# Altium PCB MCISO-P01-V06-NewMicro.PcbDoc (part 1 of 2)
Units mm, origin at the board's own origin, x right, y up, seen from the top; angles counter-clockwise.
Board outline 60 x 112.78 mm, 2 copper layers (Top Layer, Bottom Layer), stack 1.57 mm thick; 124 components, 85 nets, 520 pads, 108 vias.
Unrouted connection lines stored in the file: 6.
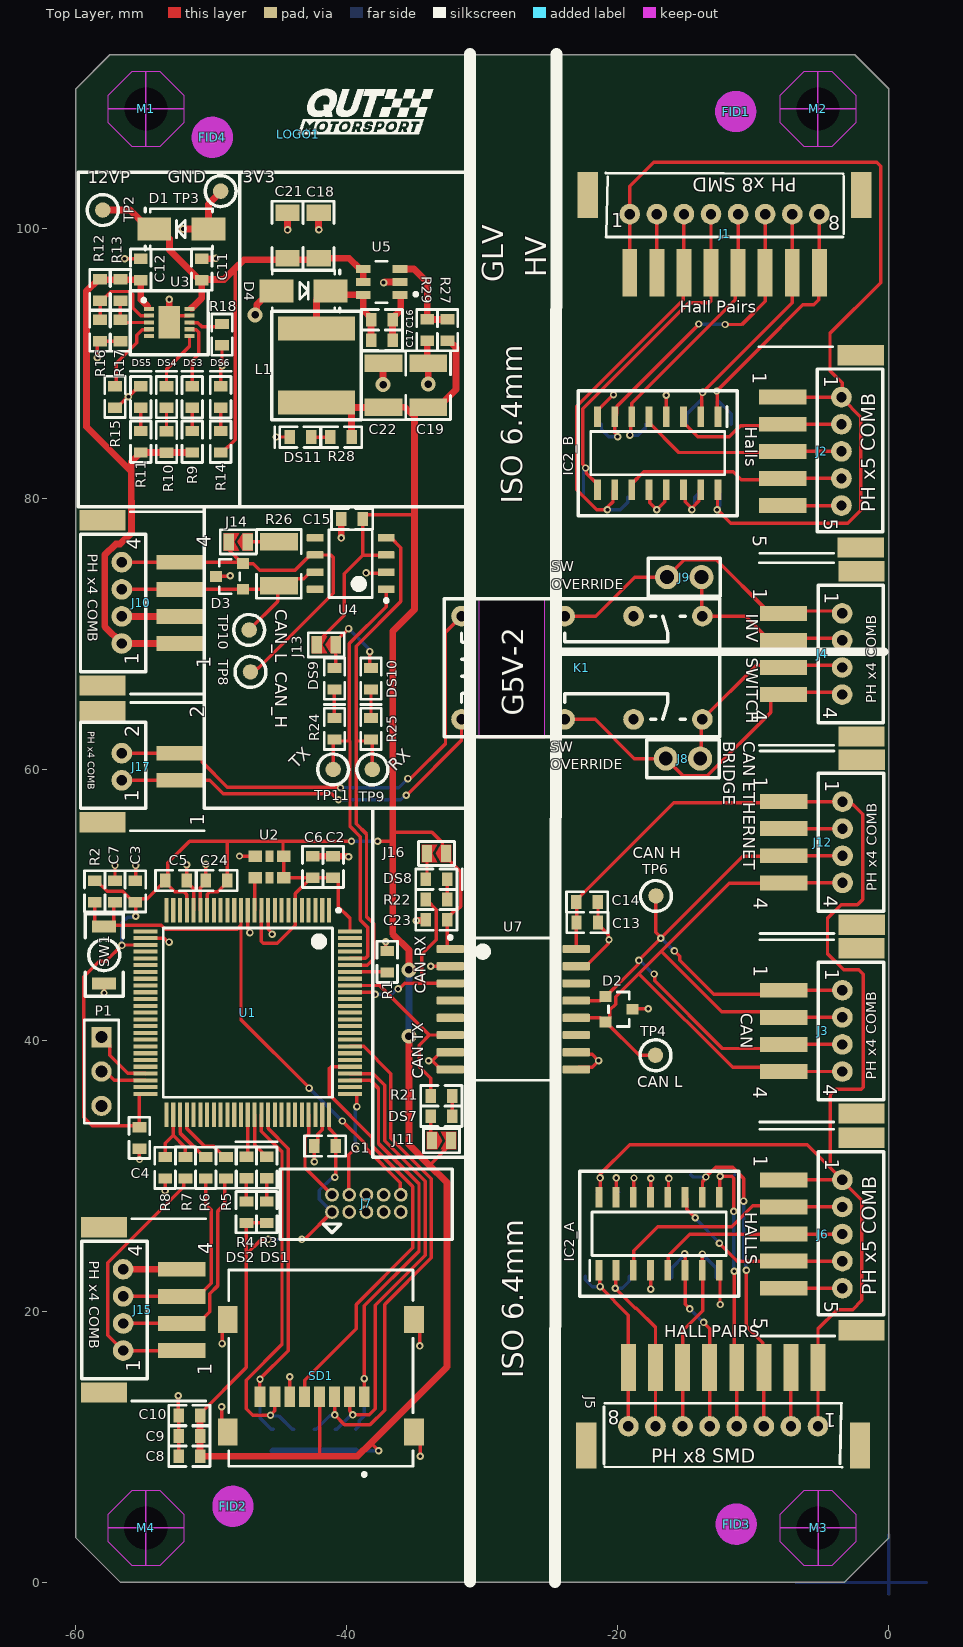
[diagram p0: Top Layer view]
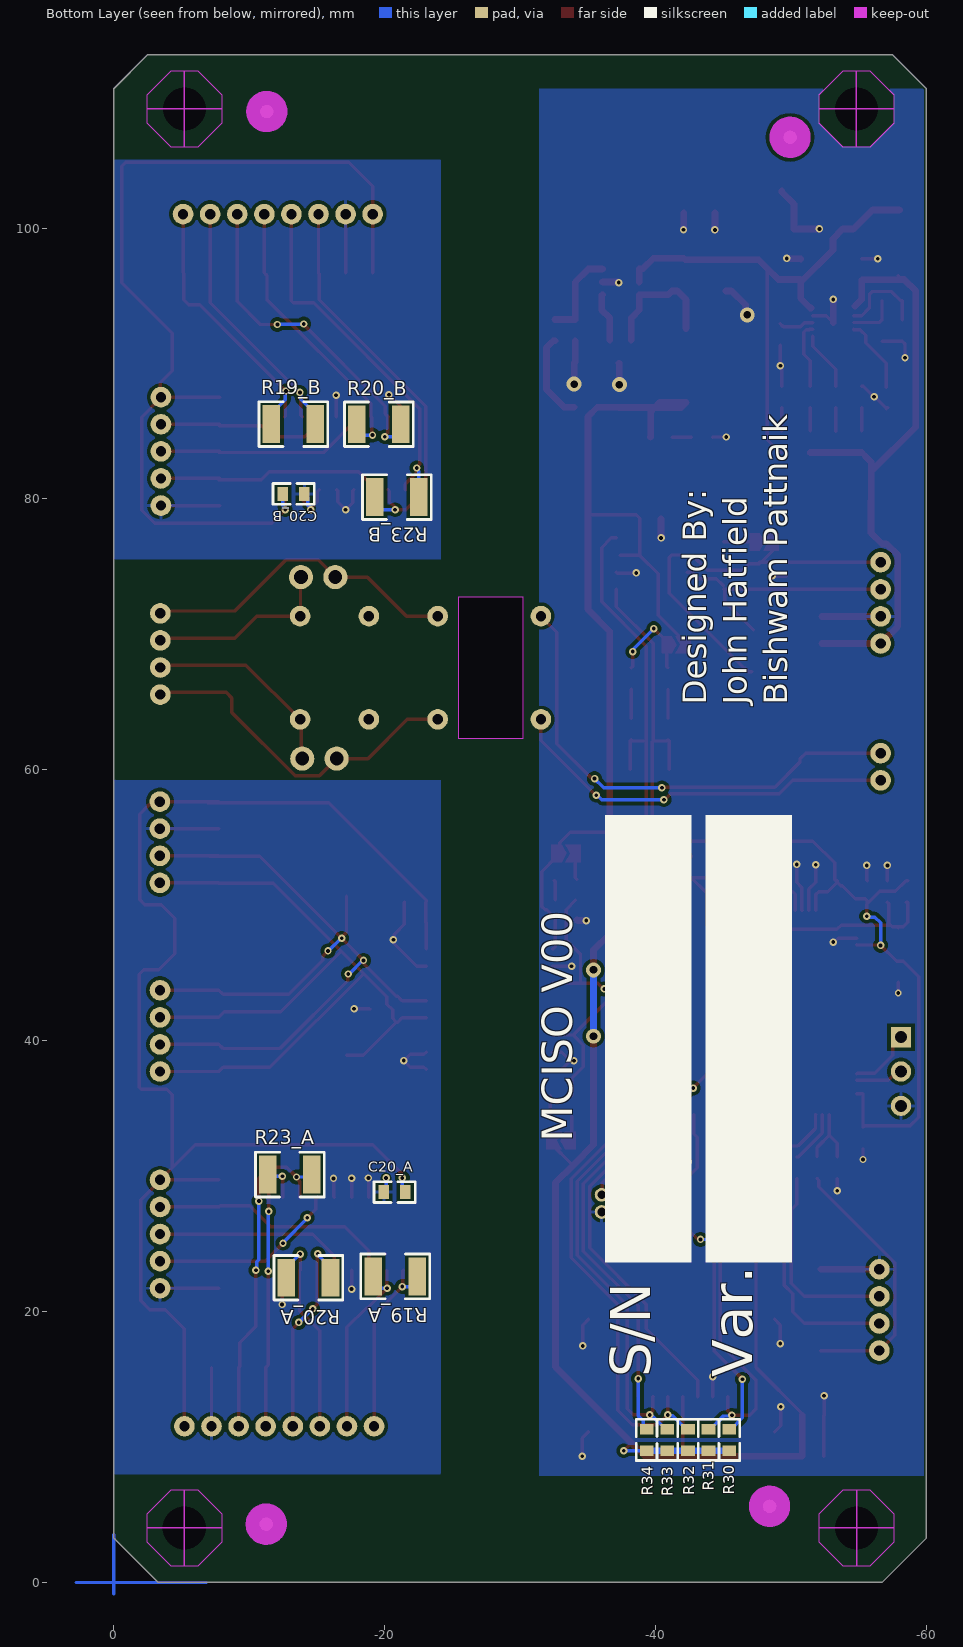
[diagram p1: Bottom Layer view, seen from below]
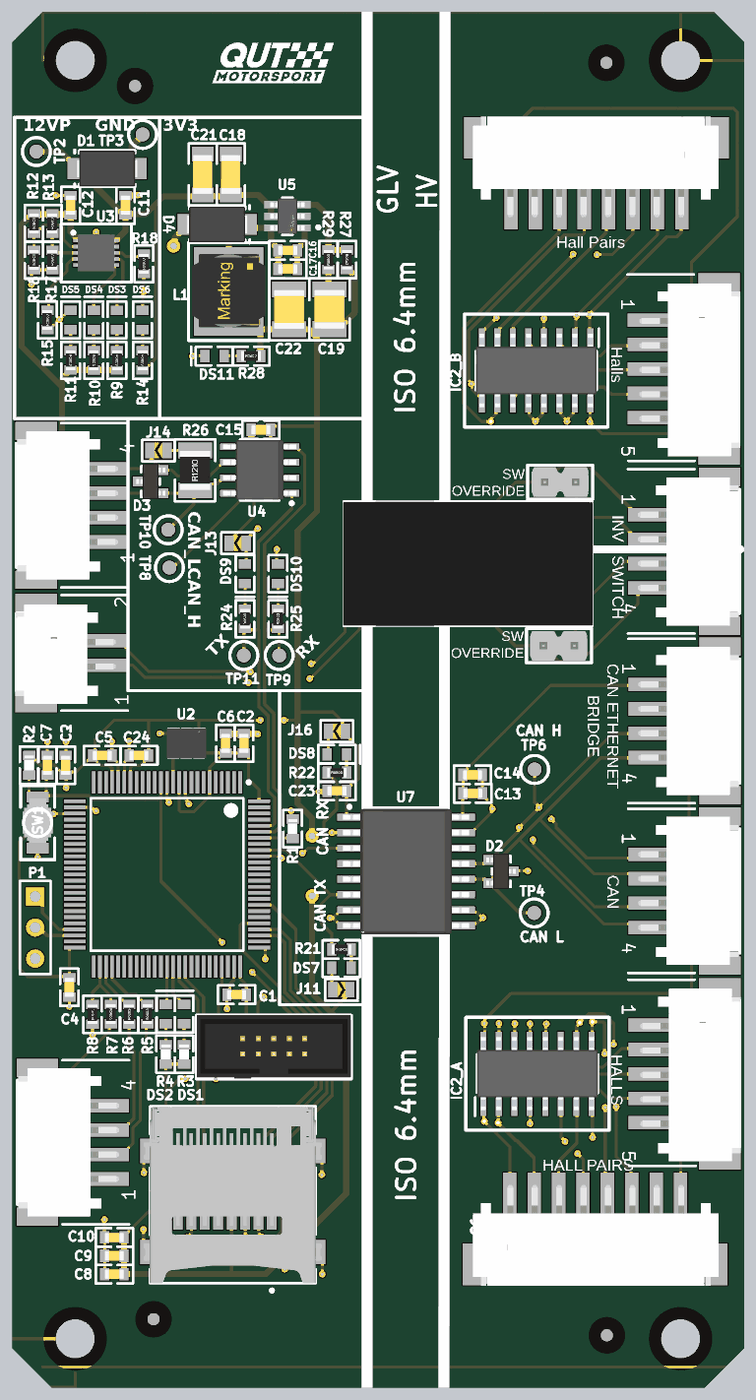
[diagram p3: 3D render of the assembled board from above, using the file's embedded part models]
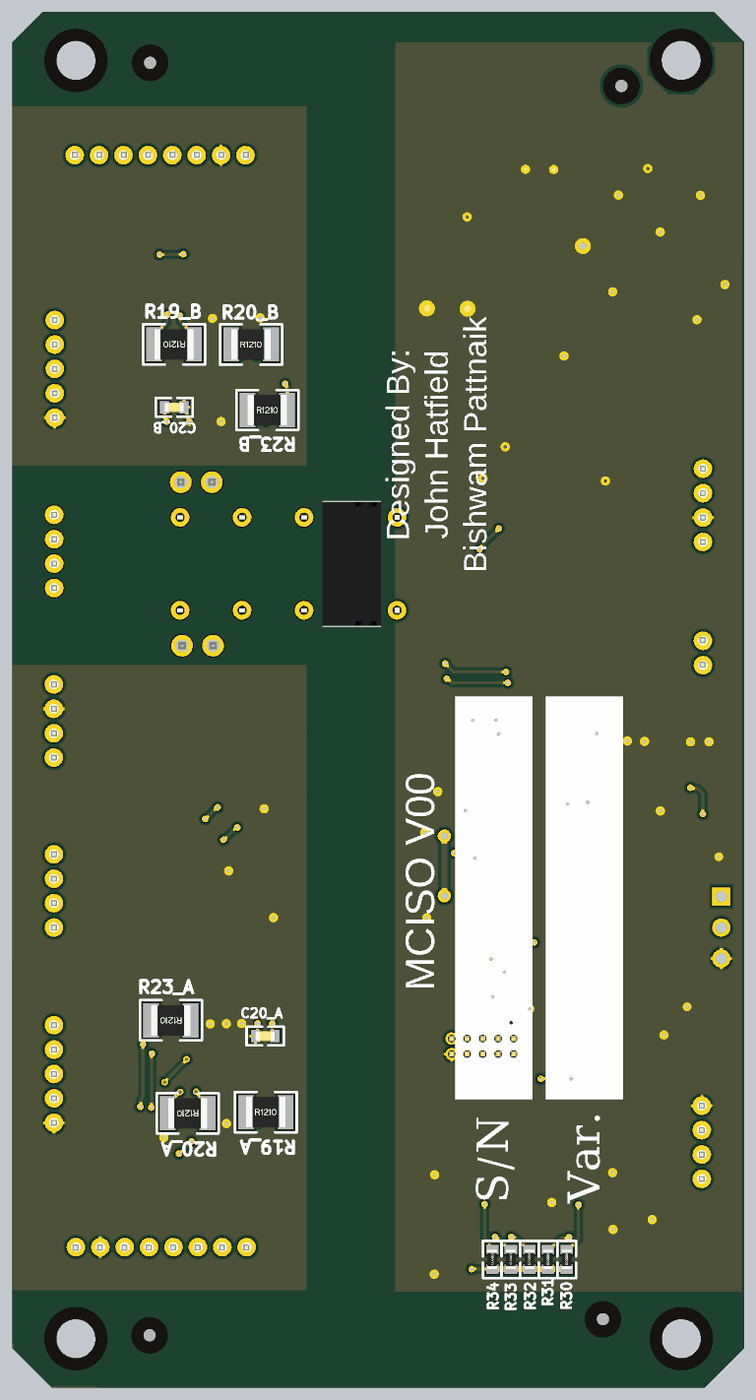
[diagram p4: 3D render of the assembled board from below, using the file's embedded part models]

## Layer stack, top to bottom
Top Solder: solder mask 0.0102, Solder Resist, Dk 3.5
Top Layer: signal copper 0.0356
Dielectric 1: core 1.4986, Core-043, Dk 4.3
Bottom Layer: signal copper 0.0356
Bottom Solder: solder mask 0.0102, Solder Resist, Dk 3.5

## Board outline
-59.993,3.287 -59.993,110.287 -57.493,112.787 -2.493,112.787 0.007,110.287 0.007,3.287 -3.276,0.004 -56.71,0.004
cut-out: -30.211,72.726 -25.411,72.726 -25.411,62.326 -30.211,62.326

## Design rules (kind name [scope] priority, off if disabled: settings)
Clearance [All] p1: gap=0.254 ignorepadtopadclearanceinfootprint=TRUE except(0: Arc-Hole Track-Hole SMDPad-Hole THPad-Hole Via-Hole Fill-Hole Poly-Hole Region-Hole Text-Hole; 0.152: SMDPad-SMDPad; 0.178: Arc-SMDPad Track-SMDPad; 0.2: Arc-Arc Arc-Track Track-Track)
MinimumSolderMaskSliver [All] p1: minsoldermaskwidth=0.1
PolygonConnect PolygonConnect_1 [All] p1: thpad.connectstyle=Relief thpad.reliefconductorwidth=0.254 thpad.reliefentries=4 thpad.polygonreliefangle="90 Angle" thpad.airgapwidth=0.254 smdpad.connectstyle=Relief smdpad.reliefconductorwidth=0.254 smdpad.reliefentries=4 smdpad.polygonreliefangle="90 Angle" smdpad.airgapwidth=0.254 via.connectstyle=Direct via.reliefconductorwidth=0.254 via.reliefentries=4 via.polygonreliefangle="90 Angle" via.airgapwidth=0.254
RoomDefinition Designator [InComponentClass('Designator')] p1 off: confinementstyle=ConfineIn formatcopy=TRUE lockcomponents=FALSE outline -43.811,-14.874 -33.411,-14.874 -33.411,-7.074 -43.811,-7.074
RoomDefinition U_MCISO-S07-V00-Master-PSU3V3-300mA [InComponentClass('U_MCISO-S07-V00-Master-PSU3V3-300mA')] p2 off: confinementstyle=ConfineIn formatcopy=TRUE lockcomponents=FALSE outline -101.811,-42.574 -51.011,-42.574 -51.011,-17.174 -101.811,-17.174
RoomDefinition U_MCISO-S05-V00-CANIsolation [InComponentClass('U_MCISO-S05-V00-CANIsolation')] p3 off: confinementstyle=ConfineIn formatcopy=TRUE lockcomponents=FALSE outline -94.011,15.426 -83.411,15.426 -83.411,22.026 -94.011,22.026
RoomDefinition U_MCISO-S04-V00-Microcontroller [InComponentClass('U_MCISO-S04-V00-Microcontroller')] p4 off: confinementstyle=ConfineIn formatcopy=TRUE lockcomponents=FALSE outline -90.611,-12.974 -82.011,-12.974 -82.011,-7.674 -90.611,-7.674
RoomDefinition U_MCISO-S03-V00-CAN_MAIN [InComponentClass('U_MCISO-S03-V00-CAN_MAIN')] p5 off: confinementstyle=ConfineIn formatcopy=TRUE lockcomponents=FALSE outline -101.311,-13.874 -91.711,-13.874 -91.711,-8.074 -101.311,-8.074
RoomDefinition U_MCISO-S02-V00-12VProtection [InComponentClass('U_MCISO-S02-V00-12VProtection')] p6 off: confinementstyle=ConfineIn formatcopy=TRUE lockcomponents=FALSE outline -51.111,-34.574 -40.811,-34.574 -40.811,-18.274 -51.111,-18.274
RoomDefinition MCISO-S01-V00-Master [InComponentClass('MCISO-S01-V00-Master')] p7 off: confinementstyle=ConfineIn formatcopy=TRUE lockcomponents=FALSE outline -76.211,-4.974 -65.611,-4.974 -65.611,-0.374 -76.211,-0.374
RoomDefinition B [InComponentClass('B')] p8 off: confinementstyle=ConfineIn formatcopy=TRUE lockcomponents=FALSE outline -89.811,-6.074 -82.111,-6.074 -82.111,-0.274 -89.811,-0.274
RoomDefinition A [InComponentClass('A')] p9 off: confinementstyle=ConfineIn formatcopy=TRUE lockcomponents=FALSE outline -101.811,-6.074 -91.511,-6.074 -91.511,0.026 -101.811,0.026
RoutingVias [All] p1: holewidth=0.35 width=0.6 viastyle="Through Hole" minholewidth=0.35 minwidth=0.6 maxholewidth=0.35 maxwidth=0.6
SilkToSilkClearance [All] p1: silktosilkclearance=0
SilkToSolderMaskClearance [IsPad] p1: minsilkscreentomaskgap=0 clearancetoexposedcopper=TRUE
SolderMaskExpansion [All] p1: expansion=0.102 istentingtop=FALSE
Width [All] p1: maxlimit=0.5 minlimit=0.254 preferedwidth=0.254
27 further rules are at their usual default settings.

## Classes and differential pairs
component class Designator: C8 C9 C10 J15 R5 R6 R7 R8 R30 R31 R32 R33 R34 SD1
component class B: C20_B IC2_B R19_B R20_B R23_B
component class A: C20_A IC2_A R19_A R20_A R23_A
channel class MCISO-S06-V00-HALL_DIFFB: "DIFF A" "DIFF B"
component class U_MCISO-S07-V00-Master-PSU3V3-300mA: C16 C17 C18 C19 C21 C22 D4 DS11 L1 R27 R28 R29 "TP 13" U5
component class U_MCISO-S03-V00-CAN_MAIN: C15 D3 DS9 DS10 J13 J14 R24 R25 R26 TP8 TP9 TP10 TP11 U4
component class U_MCISO-S02-V00-12VProtection: C11 C12 D1 DS3 DS4 DS5 DS6 R9 R10 R11 R12 R13 R14 R15 R16 R17 R18 TP2 TP3 U3
component class U_MCISO-S05-V00-CANIsolation: C13 C14 C23 D2 DS7 DS8 J11 J12 J16 R21 R22 TP4 TP6 U7
component class U_MCISO-S04-V00-Microcontroller: C1 C2 C3 C4 C5 C6 C7 C24 DS1 DS2 J7 P1 R1 R2 R3 R4 SW1 U1 U2
component class MCISO-S01-V00-Master: Connector? FID1 FID2 FID3 FID4 J1 J2 J3 J4 J5 J6 J8 J9 J10 J17 K1 LOGO1 M1 M2 M3 M4 NCM?

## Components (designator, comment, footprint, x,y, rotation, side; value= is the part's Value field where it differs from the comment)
C1 "100nF" Cap_Ceramic_0603 -41.604,32.226 r0 top
C2 "100nF" Cap_Ceramic_0603 -41.011,52.826 r270 top
C3 "100nF" Cap_Ceramic_0603 -55.611,51.026 r270 top
C4 "100nF" Cap_Ceramic_0603 -55.311,32.826 r90 top
C5 "4u7" Cap_Ceramic_0603 -52.604,51.826 r180 top
C6 "100nF 100V" Cap_Ceramic_0603 -42.511,52.826 r90 top
C7 "100nF 100V" Cap_Ceramic_0603 -57.111,51.026 r270 top
C8 "4u7" Cap_Ceramic_0603 -51.624,9.326 r0 top
C9 "1uF" Cap_Ceramic_0603 -51.624,10.826 r0 top
C10 "100nF" Cap_Ceramic_0603 -51.624,12.326 r0 top
C11 "4u7 50V 5%" Cap_Ceramic_0603 -50.711,96.926 r270 top
C12 "470nF 50V 5%" Cap_Ceramic_0603 -55.211,96.926 r270 top
C13 "100nF 50V 5% X7R 0603" Cap_Ceramic_0603 -22.245,48.725 r180 top
C14 "4u7" Cap_Ceramic_0603 -22.262,50.242 r180 top
C15 "100nF 100V" Cap_Ceramic_0603 -39.611,78.526 r180 top
C16 "100nF 50V" Cap_Ceramic_0603 -37.412,93.222 r180 top
C17 "100nF 50V" Cap_Ceramic_0603 -37.412,91.711 r180 top
C18 "22uF 35V" Cap_Ceramic_1206 -42.079,99.444 r90 top
C19 "47uF 16V 1210" Cap_Ceramic_1210 -33.988,88.399 r270 top
C20_A "0.1u" Cap_Ceramic_0603 -20.725,28.826 r180 bottom (schematic designator C20)
C20_B "0.1u" Cap_Ceramic_0603 -13.272,80.368 r0 bottom (schematic designator C20)
C21 "22uF 35V" Cap_Ceramic_1206 -44.379,99.444 r90 top
C22 "47uF 16V 1210" Cap_Ceramic_1210 -37.303,88.384 r270 top
C23 "100nF 50V 5% X7R 0603" Cap_Ceramic_0603 -33.38,48.923 r0 top
C24 "100nF" Cap_Ceramic_0603 -49.611,51.826 r0 top
D1 "1N4448WQ-7-F" SMA -52.211,99.926 r180 top
D2 "NUP2105L" NUP2105L -19.911,42.326 r270 top
D3 "NUP2105L" NUP2105L -48.661,74.276 r90 top
D4 "B260A-13-F" SMA -43.199,95.358 r0 top
DS1 "LED Orange" "LED ORANGE 0603" -45.911,30.633 r90 top
DS2 "LED Orange" "LED ORANGE 0603" -47.411,30.633 r90 top
DS3 "LED Red 0603" "LED RED 0603" -51.411,87.513 r90 top
DS4 "LED Red 0603" "LED RED 0603" -53.311,87.52 r90 top
DS5 "LED Green 0603" "LED GREEN 0603" -55.211,87.52 r90 top
DS6 "LED Green 0603" "LED GREEN 0603" -49.311,87.52 r90 top
DS7 "LED Blue 0603" "LED BLUE 0603" -33.011,34.426 r0 top
DS8 "LED Blue 0603" "LED BLUE 0603" -33.38,51.923 r0 top
DS9 "LED Blue 0603" "LED BLUE 0603" -40.911,66.726 r270 top
DS10 "LED Blue 0603" "LED BLUE 0603" -38.211,66.726 r270 top
DS11 "LED Green 0603" "LED GREEN 0603" -43.418,84.562 r180 top
FID1 "Fiducial 1MM" "FIDUCIAL 1MM" -11.294,108.599 r90 top
FID2 "Fiducial 1MM" "FIDUCIAL 1MM" -48.411,5.626 r90 top
FID3 "Fiducial 1MM" "FIDUCIAL 1MM" -11.253,4.308 r0 top
FID4 "Fiducial 1MM" "FIDUCIAL 1MM" -49.927,106.696 r90 top
IC2_A "AM26LS32ACDR" 16PinHallFootprint -16.915,25.749 r90 top (schematic designator IC2)
IC2_B "AM26LS32ACDR" 16PinHallFootprint -17.075,83.373 r270 top (schematic designator IC2)
J1 "JST PH 8x Right comb" "JST PH 8x RIGHT SMD" -14.111,103.936 r0 top
J2 "JST PH 5x RIGHT COMB" "JST PH 5x RIGHT COMB" -0.557,84.511 r270 top
J3 "JST PH 4x RIGHT COMB" "JST PH 4x RIGHT COMB" -0.49,40.726 r270 top
J4 "JST PH 4x RIGHT COMB" "JST PH 4x RIGHT COMB" -0.508,68.554 r270 top
J5 "JST PH 8x Right comb" "JST PH 8x RIGHT SMD" -10.211,8.626 r180 top
J6 "JST PH 5x RIGHT COMB" "JST PH 5x RIGHT COMB" -0.49,26.726 r270 top
J7 "IDC 10P 2x5 1.27mm" "IDC 1.27MM 10P" -38.551,27.991 r0 top
J8 "Jumper 2Way Pins" Jumper_2Way_Pin -13.911,60.826 r0 top
J9 "Jumper 2Way Pins" Jumper_2Way_Pin -16.351,74.226 r180 top
J10 "JST PH 4x RIGHT COMB" "JST PH 4x RIGHT COMB" -59.532,72.326 r90 top
J11 "Jumper 2Way Solderable" Jumper_2Way_Solderable -33.708,32.626 r270 top
J12 "JST PH 4x RIGHT COMB" "JST PH 4x RIGHT COMB" -0.48,54.653 r270 top
J13 "Jumper 2Way Solderable" Jumper_2Way_Solderable -40.814,69.226 r90 top
J14 "Jumper 2Way Solderable" Jumper_2Way_Solderable -47.311,76.826 r90 top
J15 "JST PH 4x RIGHT COMB" "JST PH 4x RIGHT COMB" -59.432,20.126 r90 top
J16 "Jumper 2Way Solderable" Jumper_2Way_Solderable -32.68,53.823 r90 top
J17 "JST PH 2x RIGHT COMB" "JST PH 2x RIGHT COMB" -59.532,62.226 r90 top
K1 "G5V-2-DC12" G5V-2 -22.641,67.536 r0 top
L1 "74404064221" Inductor_6x6mm -42.244,89.91 r270 top
LOGO1 "50mm Wide QUTMS Logo" "QUTMS LOGO 10MM" -43.589,106.929 r0 top
M1 "Hole M3 Tight Unplated" "M3.2 UNPLATED" -54.824,108.791 r0 top
M2 "Hole M3 Tight Unplated" "M3.2 UNPLATED" -5.216,108.791 r0 top
M3 "Hole M3 Tight Unplated" "M3.2 UNPLATED" -5.209,4.027 r0 top
M4 "Hole M3 Tight Unplated" "M3.2 UNPLATED" -54.834,4.027 r0 top
P1 "Header 3" HDR1X3 -58.111,40.266 r270 top
R1 "10k 1% 0603" Res_ThinFilm_0603 -37.011,45.826 r90 top
R2 "4k7" Res_ThinFilm_0603 -58.611,51.026 r90 top
R3 "330R" Res_ThinFilm_0603 -45.911,27.338 r270 top
R4 "330R" Res_ThinFilm_0603 -47.411,27.338 r270 top
R5 "22R" Res_ThinFilm_0603 -48.911,30.626 r90 top
R6 "22R" Res_ThinFilm_0603 -50.411,30.62 r90 top
R7 "10k 5% 0603" Res_ThinFilm_0603 -51.911,30.626 r270 top
R8 "15k 5% 0603" Res_ThinFilm_0603 -53.411,30.62 r90 top
R9 "4k7 5% 0603" Res_ThinFilm_0603 -51.411,84.22 r270 top
R10 "4k7 5% 0603" Res_ThinFilm_0603 -53.311,84.213 r270 top
R11 "4k7 5% 0603" Res_ThinFilm_0603 -55.211,84.22 r270 top
R12 "2M2 1%" Res_ThinFilm_0603 -58.211,95.42 r90 top
R13 "2M2 1%" Res_ThinFilm_0603 -56.711,95.42 r90 top
R14 "4k7 5% 0603" Res_ThinFilm_0603 -49.311,84.22 r270 top
R15 "150k 5% 0603" Res_ThinFilm_0603 -57.111,87.526 r90 top
R16 "390k 5%" Res_ThinFilm_0603 -58.211,92.433 r90 top
R17 "240k 5%" Res_ThinFilm_0603 -56.711,92.433 r90 top
R18 "1k 5% 0603" Res_ThinFilm_0603 -49.211,92.126 r90 top
R19_A "120R 1% 1210" Res_ThinFilm_1210 -20.776,22.599 r180 bottom (schematic designator R19)
R19_B "120R 1% 1210" Res_ThinFilm_1210 -13.256,85.522 r0 bottom (schematic designator R19)
R20_A "120R 1% 1210" Res_ThinFilm_1210 -14.367,22.499 r0 bottom (schematic designator R20)
R20_B "120R 1% 1210" Res_ThinFilm_1210 -19.571,85.513 r180 bottom (schematic designator R20)
R21 "330R" Res_ThinFilm_0603 -33.011,35.926 r0 top
R22 "330R" Res_ThinFilm_0603 -33.38,50.423 r0 top
R23_A "120R 1% 1210" Res_ThinFilm_1210 -12.991,30.119 r0 bottom (schematic designator R23)
R23_B "120R 1% 1210" Res_ThinFilm_1210 -20.898,80.136 r180 bottom (schematic designator R23)
R24 "330R" Res_ThinFilm_0603 -40.911,63.026 r90 top
R25 "330R" Res_ThinFilm_0603 -38.211,63.026 r90 top
R26 "120R 1% 1210" Res_ThinFilm_1210 -45.011,75.201 r90 top
R27 "64k9 1%" Res_ThinFilm_0603 -32.566,92.462 r270 top
R28 "1k" Res_ThinFilm_0603 -40.418,84.562 r0 top
R29 "19k6 1%" Res_ThinFilm_0603 -34.066,92.462 r90 top
R30 "10k 5% 0603" Res_ThinFilm_0603 -45.441,10.524 r270 bottom
R31 "10k 5% 0603" Res_ThinFilm_0603 -43.906,10.524 r270 bottom
R32 "10k 5% 0603" Res_ThinFilm_0603 -42.388,10.524 r270 bottom
R33 "10k 5% 0603" Res_ThinFilm_0603 -40.862,10.524 r270 bottom
R34 "10k 5% 0603" Res_ThinFilm_0603 -39.337,10.524 r270 bottom
SD1 "47219-2001" MOLX-47219-2001-8_V -41.916,15.276 r180 top
SW1 "B3U-1000P" "BTN B3U-1000P" -57.911,46.326 r90 top
TP2 "TestPoint" TestPointSMD -58.011,101.326 r90 top
TP3 "TestPoint" TestPointSMD -49.311,102.726 r0 top
TP4 "TestPoint_SMD" TestPointSMD -17.211,38.926 r270 top
TP6 "TestPoint_SMD" TestPointSMD -17.175,50.686 r0 top
TP8 "TestPoint_SMD" TestPointSMD -47.111,67.226 r180 top
TP9 "TestPoint_SMD" TestPointSMD -38.111,60.026 r0 top
TP10 "TestPoint_SMD" TestPointSMD -47.211,70.326 r180 top
TP11 "TestPoint_SMD" TestPointSMD -41.011,60.026 r90 top
U1 "STM32F207VGT7" STM-LQFP100_N -47.311,42.076 r270 top
U2 "DSC1101CI5-020.0000T" VDFN6_3P2X2P5_MCH -45.711,52.826 r270 top
U3 "MAX17612A" MAX17612A -53.111,93.026 r0 top
U4 "SN65HVD232D" D0008A_L -39.711,75.226 r180 top
U5 "LMR14010ADDCR" FP-DDC0006A-MFG -37.435,96.017 r180 top
U7 "ISO1050DWR" DW00016B_V -27.711,42.326 r0 top

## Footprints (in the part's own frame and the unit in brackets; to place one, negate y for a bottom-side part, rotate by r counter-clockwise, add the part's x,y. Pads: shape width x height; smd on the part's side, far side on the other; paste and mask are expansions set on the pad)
16PinHallFootprint [mm]
  rect 1.5x0.5 smd: 1(-2.7,4.47) 2(-2.7,3.2) 3(-2.7,1.93) 4(-2.7,0.66) 5(-2.7,-0.61) 6(-2.7,-1.88) 7(-2.7,-3.15) 8(-2.7,-4.42) 9(2.7,-4.42) 10(2.7,-3.15) 11(2.7,-1.88) 12(2.7,-0.61) 13(2.7,0.66) 14(2.7,1.93) 15(2.7,3.2) 16(2.7,4.47)
  silkscreen extent -4.62,-5.85 4.62,5.9, body extent -3,-4.92 3,4.98, height 1.75
"BTN B3U-1000P" [mil] "OMRON B3U-1000P"
  rect 35x70 smd: 1(-82.68,0) 2(82.68,0)
  silkscreen extent -120,-55 120,55, body extent -79,-49 79,49
Cap_Ceramic_0603 [mil]
  rect 30x40 smd: 1(-31.24,0) 2(31.24,0)
  silkscreen extent -60,-30 60,30, body extent -31,-16 31,16, height 33
Cap_Ceramic_1206 [mil]
  rect 47x71 smd: 1(-66.08,0) 2(66.08,0)
  silkscreen extent -100,-45 100,45, body extent -63,-31 63,32, height 53
Cap_Ceramic_1210 [mm]
  rect 1.3x2.8 smd: 1(-1.625,0) 2(1.625,0)
  silkscreen extent -2.54,-1.65 2.54,1.65, body extent -1.6,-1.25 1.6,1.25, height 1.35
D0008A_L [mm] "SOIC, 8-Leads, Body 5x4mm, Pitch 1.27mm, IPC High Density"
  rrect18% 1.25x0.55 smd: 1(-2.625,1.905) 2(-2.625,0.635) 3(-2.625,-0.635) 4(-2.625,-1.905) 5(2.625,-1.905) 6(2.625,-0.635) 7(2.625,0.635) 8(2.625,1.905)
  silkscreen extent -2.75,-2.5 1.6,2.85, body extent -3,-2.45 3,2.45, height 1.63
DW00016B_V [mm] "SOIC, 16-Leads, Body 10.3x7.5mm, Pitch 1.27mm"
  rrect17% 2x0.6 smd: 1(-4.65,4.445) 2(-4.65,3.175) 3(-4.65,1.905) 4(-4.65,0.635) 5(-4.65,-0.635) 6(-4.65,-1.905) 7(-4.65,-3.175) 8(-4.65,-4.445) 9(4.65,-4.445) 10(4.65,-3.175) 11(4.65,-1.905) 12(4.65,-0.635) 13(4.65,0.635) 14(4.65,1.905) 15(4.65,3.175) 16(4.65,4.445)
  silkscreen extent -4.77,-5.25 3.25,5.42, body extent -5.17,-5.15 5.17,5.15, height 2.59
"FIDUCIAL 1MM" [mm]
  round 1 smd mask+1: 1(0,0)
  round 1 smd far side mask+1: 1(0,0)
  Keep-Out Layer circle w1.524: c0,0 r0.762
FP-DDC0006A-MFG [mm]
  rect 1.1x0.6 smd paste+0 mask+0: 1(-1.35,0.95) 2(-1.35,0) 3(-1.35,-0.95) 4(1.35,-0.95) 5(1.35,0) 6(1.35,0.95)
  silkscreen extent -2.65,-1.53 0.43,1.53, body extent -2,-1.63 2,1.63, height 0.25
G5V-2 [mil]
  round 60 hole 30: 1(-350,150) 4(-50,150) 6(150,150) 8(350,150) 9(350,-150) 11(150,-150) 13(-50,-150) 16(-350,-150)
  silkscreen extent -400,-200 400,200, body extent -404,-199 404,199, height 453
HDR1X3 [mm] "Connector; Header; 3 Position"
  rect 1.5x1.5 hole 0.9: 1(0,0)
  round 1.5 hole 0.9: 2(2.54,0) 3(5.08,0)
  silkscreen extent -1.27,-1.27 6.35,1.27
"IDC 1.27MM 10P" [mil]
  round 40 hole 25: 1(-100,-25) 2(-100,25) 3(-50,-25) 4(-50,25) 5(0,-25) 6(0,25) 7(50,-25) 8(50,25) 9(100,-25) 10(100,25)
  silkscreen extent -250,-105 250,100, body extent -249,-104 249,100, height 214
Inductor_6x6mm [mm]
  rect 1.8x5.7 smd: 1(-2.667,0) 2(2.794,0)
  silkscreen extent -3.94,-3.3 4.06,3.3, body extent -3,-3 3,3, height 4.56
"JST PH 2x RIGHT COMB" [mm]
  round 1.524 hole 0.762: 1(-3,-2.921) 2(-1,-2.921)
  rect 1.1x3.5 smd: 1(-3,-7.25) 2(-1,-7.25)
  rect 1.5x3.4 smd: M(-6.1,-1.5) M(2.1,-1.5)
  silkscreen extent -6.73,-9.04 2.75,0.13, body extent -6.17,-8.03 1.97,0.23, height 5.89
"JST PH 4x RIGHT COMB" [mm]
  round 1.524 hole 0.762: 1(-3,-2.921) 2(-1,-2.921) 3(1,-2.921) 4(3,-2.921)
  rect 1.1x3.5 smd: 1(-3,-7.25) 2(-1,-7.25) 3(1,-7.25) 4(3,-7.25)
  rect 1.5x3.4 smd: M(-6.1,-1.5) M(6.1,-1.5)
  silkscreen extent -6.73,-9.02 6.73,0.13, body extent -6.07,-8.2 6.07,0.06, height 5.89
"JST PH 5x RIGHT COMB" [mm]
  round 1.524 hole 0.762: 1(-3,-2.921) 2(-1,-2.921) 3(1,-2.921) 4(3,-2.921) 5(5,-2.921)
  rect 1.1x3.5 smd: 1(-3,-7.25) 2(-1,-7.25) 3(1,-7.25) 4(3,-7.25) 5(5,-7.25)
  rect 1.5x3.4 smd: M(-6.1,-1.5) M(8.1,-1.5)
  silkscreen extent -6.73,-9.02 8.53,0.13, body extent -6,-8.03 8.15,0.23, height 5.89
"JST PH 8x RIGHT SMD" [mm]
  rect 1.1x3.5 smd: 1(-5,-7.25) 2(-3,-7.25) 3(-1,-7.25) 4(1,-7.25) 5(3,-7.25) 6(5,-7.25) 7(7,-7.25) 8(9,-7.25)
  round 1.524 hole 0.762: 1(-5,-2.91) 2(-3,-2.91) 3(-1,-2.91) 4(1,-2.91) 5(3,-2.91) 6(5,-2.91) 7(7,-2.91) 8(9,-2.91)
  rect 1.5x3.4 smd: M(-8.1,-1.5) M(12.1,-1.5)
  silkscreen extent -6.78,-4.6 10.8,0.13, body extent -8.12,-8 12.03,0.25, height 5.89
Jumper_2Way_Pin [mil]
  round 70 hole 40: 1(-100,0) 2(0,0)
  silkscreen extent -155,-55 55,55, body extent -142,-48 42,47, height 332
Jumper_2Way_Solderable [mil]
  rect 50x30 smd: 1(0,55) 2(0,0)
  Top Layer region: -25,25 0,40 25,25 25,70 -25,70
  Top Layer region: -25,15 0,30 25,15 25,-15 0,-15 -25,-15
  silkscreen extent -35,-25 35,80
"LED BLUE 0603" [mil]
  rect 30x40 smd: 1(-31.24,0) 2(31.24,0)
  silkscreen extent -60,-30 75,30, body extent -40,-20 40,20, height 30
"LED GREEN 0603" [mil]
  rect 30x40 smd: 1(-31.24,0) 2(31.24,0)
  silkscreen extent -60,-30 75,30, body extent -40,-20 40,20, height 30
"LED ORANGE 0603" [mil]
  rect 30x40 smd: 1(-31.24,0) 2(31.24,0)
  silkscreen extent -60,-30 75,30, body extent -40,-20 40,20, height 30
"LED RED 0603" [mil]
  rect 30x40 smd: 1(-31.24,0) 2(31.24,0)
  silkscreen extent -60,-30 75,30, body extent -40,-20 40,20, height 30
"M3.2 UNPLATED" [mm]
  round 0 hole 3.2 unplated mask+2.6: 1(0,0)
  Keep-Out Layer pour cut-out: -2.794,0 -2.794,1.016 -1.016,2.794 0,2.794 0,0
  Keep-Out Layer pour cut-out: 0,2.794 1.016,2.794 2.794,1.016 2.794,0 0,0
  Keep-Out Layer pour cut-out: 2.794,0 2.794,-1.016 1.016,-2.794 0,-2.794 0,0
  Keep-Out Layer pour cut-out: 0,-2.794 -1.016,-2.794 -2.794,-1.016 -2.794,0 0,0
MAX17612A [mm]
  rect 0.75x0.3 smd: 1(-1.5,1) 2(-1.5,0.5) 3(-1.5,0) 4(-1.5,-0.5) 5(-1.5,-1) 6(1.5,-1) 7(1.5,-0.5) 8(1.5,0) 9(1.5,0.5) 10(1.5,1)
  rect 1.6x2.4 smd: 11(0,0)
  silkscreen extent -2.87,-2.4 2.87,2.35, body extent -1.55,-1.5 1.55,1.5, height 0.8
MOLX-47219-2001-8_V [mm] "CONN, 8-Leads, Body 14.5x13.6mm, Pitch 1.1mm"
  rect 0.8x1.5 smd: 1(-3.205,1.55) 2(-2.105,1.55) 3(-1.005,1.55) 4(0.095,1.55) 5(1.195,1.55) 6(2.295,1.55) 7(3.395,1.55) 8(4.495,1.55)
  rect 1.45x2 smd: 9(6.875,4.15) 10(6.875,-4.15) 11(-6.875,-4.15) 12(-6.875,4.15)
  silkscreen extent -6.8,-7.8 6.8,7.42, body extent -7.3,-7.79 7.3,6.71, height 1.91
NUP2105L [mm]
  rect 0.8x0.9 smd: 1(-0.95,-1) 2(0.95,-1) 3(0,1)
  silkscreen extent -1.27,-0.76 1.27,0.76, body extent -1.45,-1.22 1.45,1.18, height 1
"QUTMS LOGO 10MM" [mm]
  silkscreen extent 0,0 9.96,3.34
Res_ThinFilm_0603 [mil]
  rect 30x40 smd: 1(-31.24,0) 2(31.24,0)
  silkscreen extent -60,-30 60,30, body extent -31,-16 31,16
Res_ThinFilm_1210 [mm]
  rect 1.3x2.8 smd: 1(-1.625,0) 2(1.625,0)
  silkscreen extent -2.54,-1.65 2.54,1.65, body extent -1.6,-1.25 1.6,1.25, height 0.6
SMA [mm]
  rect 2.5x1.7 smd: A(-2,0) K(2,0)
  silkscreen extent -2.3,-1.52 2.67,1.52, body extent -2.52,-1.46 2.52,1.46, height 2.4
STM-LQFP100_N [mm] "Thin QFP, 100-Leads, Body 14x14mm, Pitch 0.5mm, IPC Medium Density"
  rect 1.8x0.3 smd: 1(-7.55,6) 2(-7.55,5.5) 3(-7.55,5) 4(-7.55,4.5) 5(-7.55,4) 6(-7.55,3.5) 7(-7.55,3) 8(-7.55,2.5) 9(-7.55,2) 10(-7.55,1.5) 11(-7.55,1) 12(-7.55,0.5) 13(-7.55,0) 14(-7.55,-0.5) 15(-7.55,-1) 16(-7.55,-1.5) 17(-7.55,-2) 18(-7.55,-2.5) 19(-7.55,-3) 20(-7.55,-3.5) 21(-7.55,-4) 22(-7.55,-4.5) 23(-7.55,-5) 24(-7.55,-5.5) 25(-7.55,-6) 51(7.55,-6) 52(7.55,-5.5) 53(7.55,-5) 54(7.55,-4.5) 55(7.55,-4) 56(7.55,-3.5) 57(7.55,-3) 58(7.55,-2.5) 59(7.55,-2) 60(7.55,-1.5) 61(7.55,-1) 62(7.55,-0.5) 63(7.55,0) 64(7.55,0.5) 65(7.55,1) 66(7.55,1.5) 67(7.55,2) 68(7.55,2.5) 69(7.55,3) 70(7.55,3.5) 71(7.55,4) 72(7.55,4.5) 73(7.55,5) 74(7.55,5.5) 75(7.55,6)
  rect 0.3x1.8 smd: 26(-6,-7.55) 27(-5.5,-7.55) 28(-5,-7.55) 29(-4.5,-7.55) 30(-4,-7.55) 31(-3.5,-7.55) 32(-3,-7.55) 33(-2.5,-7.55) 34(-2,-7.55) 35(-1.5,-7.55) 36(-1,-7.55) 37(-0.5,-7.55) 38(0,-7.55) 39(0.5,-7.55) 40(1,-7.55) 41(1.5,-7.55) 42(2,-7.55) 43(2.5,-7.55) 44(3,-7.55) 45(3.5,-7.55) 46(4,-7.55) 47(4.5,-7.55) 48(5,-7.55) 49(5.5,-7.55) 50(6,-7.55) 76(6,7.55) 77(5.5,7.55) 78(5,7.55) 79(4.5,7.55) 80(4,7.55) 81(3.5,7.55) 82(3,7.55) 83(2.5,7.55) 84(2,7.55) 85(1.5,7.55) 86(1,7.55) 87(0.5,7.55) 88(0,7.55) 89(-0.5,7.55) 90(-1,7.55) 91(-1.5,7.55) 92(-2,7.55) 93(-2.5,7.55) 94(-3,7.55) 95(-3.5,7.55) 96(-4,7.55) 97(-4.5,7.55) 98(-5,7.55) 99(-5.5,7.55) 100(-6,7.55)
  silkscreen extent -7.67,-6.25 6.25,6.83, body extent -7,-7 7,7, height 1.6
TestPointSMD [mil]
  round 45 smd: 1(0,0)
  silkscreen extent -45,-45 45,45
VDFN6_3P2X2P5_MCH [mm]
  rect 0.85x1 smd paste-0.425 mask+0: 1(-0.8,1.05) 3(-0.8,-1.05) 4(0.8,-1.05) 6(0.8,1.05)
  rect 0.85x0.6 smd paste+0 mask+0: 2(-0.8,0) 5(0.8,0)
  body extent -1.25,-1.6 1.25,1.6, height 0.65

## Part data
C1 C2 C3 C4 C10 C16 C17 C24: library part "100nF 50V 5% X7R 0603", "Capacitor, Ceramic, SMD, 100nF, 50V, 5%, X7R, 0603"
C5 C8 C11 C14 C20_A C20_B: library part "4u7 50V 5% X7R 0603", "Capacitor, Ceramic, SMD, 4u7, 50V, 5%, X7R, 0603"
C6 C7 C15: library part "100nF 100V 5% X7R 0603", "Capacitor, Ceramic, SMD, 100nF, 100V, 5%, X7R, 0603"
C9: library part "1uF 25V 5% X7R 0603", "Capacitor, Ceramic, SMD, 1uF, 25V, 5%, X7R, 0603"
C12: library part "470nF 50V 5% X7R 0603", "Capacitor, Ceramic, SMD, 470nF, 50V, 5%, X7R, 0603"
C13 C23: "Capacitor, Ceramic, SMD, 100nF, 50V, 5%, X7R, 0603"
C18 C21: library part "22uF 35V 20% X5R 1206", "22µF ±20% 35V Ceramic Capacitor X5R 1206 (3216 Metric)"
C19 C22: library part "47uF 16V 10% X7R 1210", "Capacitor, Ceramic, SMD, 47uF, 16V, 5%, X7R, 1210"
D1: "Diode, SMD, 75V, 5%, 250mA, SOD123", Average Rectified Current=150mA, Forward Voltage=1V, Manufacturer="ON Semiconductor / Fairchild", Manufacturer Part Number=1N914BWS, Max Forward Surge Current (Ifsm)=4A, Max Operating Temperature=150°C, Max Repetitive Reverse Voltage (Vrrm)=75V, Max Reverse Leakage Current=5uA, Min Operating Temperature=-55°C, Package Quantity=1, Power Dissipation=200mW
D4: "Diode, Schottky Barrier Rectifier, 60 V, 2 A, B260A-13-F"
DS1 DS2: library part "LED ORANGE 0603"
DS7 DS8 DS9 DS10: library part "LED BLUE 0603"
IC2_A IC2_B: "Integrated Circuit", Manufacturer_Name="Texas Instruments", Mouser Part Number=595-AM26LS32ACDR
J4: library part "JST PH 4x RIGHT COMB_1"
J8 J9: library part "Jumper 2Way Side Pins", "Jumper 2Way Side Pins"
J11 J13 J14 J16: library part "Jumper 2Way Side Solderable", "Jumper 2Way Side Solderable"
J12: "CAN Ethernet Bridge Port"
K1: "General Purpose Relay DPDT (2 Form C) Through Hole, 12V, 2A"
L1: "FIXED IND 220UH 660MA 850 MOHM"
LOGO1: library part "QUTMS Logo 50mm"
M1 M2 M3 M4: "M3.2 Hole, No Plating"
P1: "Header, 3-Pin"
R1: library part "20k 1% 0603", "Resistor, SMD, 20k, 0.1W, 5%, 0603"
R2: library part "4k7 5% 0603", "Resistor, SMD, 4k7, 0.1W, 5%, 0603"
R3 R4 R21 R22 R24 R25: library part "330R 5% 0603", "Resistor, SMD, 330R, 0.1W, 5%, 0603"
R5 R6: library part "22R 1% 0603", "Resistor, SMD, 22R, 0.1W, 1%, 0603"
R7 R30 R31 R32 R33 R34: "Resistor, SMD, 10k, 0.1W, 5%, 0603"
R8: "Resistor, SMD, 15k, 0.1W, 5%, 0603"
R9 R10 R11 R14: "Resistor, SMD, 4k7, 0.1W, 5%, 0603"
R12 R13: library part "2M2 1% 0603", "Resistor, SMD, 2M2, 0.125W, 1%, 0603"
R15: library part "150k 5%, 0603", "Resistor, SMD, 150k, 0.1W, 5%, 0603"
R16: library part "390k 5% 0603", "Resistor, SMD, 390k, 0.1W, 5%, 0603"
R17: library part "240k 5% 0603", "Resistor, SMD, 240k, 0.1W, 5%, 0603"
R18: "Resistor, SMD, 1k, 0.1W, 5%, 0603"
R19_A R19_B R20_A R20_B R23_A R23_B R26: "Resistor, SMD, 120R, 0.25W, 1%, 1210"
R27: library part "64k9 1% 0603", "Resistor, SMD, 64k9, 0.1W, 5%, 0603"
R28: library part "1k 5% 0603", "Resistor, SMD, 1k, 0.1W, 5%, 0603"
R29: library part "19k6 1% 0603", "Resistor, SMD, 19k6, 0.1W, 5%, 0603"
SD1: library part CMP-2000-05245-1, "MicroSD Card Connector, Hinge Type, -40 to 85 degC, 8-Pin SMD, RoHS, Tape and Reel", Current Rating=500mA, Manufacturer=Molex, Voltage Rating=100VDC
SW1: library part "BTN B3U-1000P", "Omron B3U-1000P Ultra Miniture Switch"
U1: library part STM32F207VGT7-Custom, "ARM Cortex-M3 32-bit MCU, 1024 KB Flash, 128 KB Internal RAM, 82 I/Os, 100-pin LQFP, -40 to 105 degC, Tray", I/Os (High Current)=82, Operating Frequency(F) (Processor speed) (MHz)=120, Supply Voltage(Vcc) min (V)=1.8
U2: "No Description Available"
U3: "4.5V to 60V, 250mA Current-Limiter with OV, UV, and Reverse Protection"
U4: library part CMP-0315-00073-2, "3.3 V CAN Transceiver, 17 mA, -40 to 85 degC, 8-pin SOIC (D), Green (RoHS & no Sb/Br)", Drivers Per Package=1, Manufacturer="Texas Instruments", Rating=Catalog, Supply Voltage(s)(V)=3.3
U5: library part CMP-04918-000056-1, "IC REG BUCK ADJ 1A TSOT23-6", Manufacturer="Texas Instruments", Max Junction Temp=+125°C, Max Supply Voltage=40V, Min Supply Voltage=4V, Output Current=1A, Package=DDC0006A, Switching Frequency=700kHz, Temperature="-40°C to +125°C", Temperature Range Low=-40°C
U7: "Isolated CAN Transceiver, -55 to 105 degC, 16-pin SOIC (DW), Green (RoHS & no Sb/Br)", Drivers Per Package=1, Manufacturer="Texas Instruments", Rating=Catalog

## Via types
v1: diameter 0.55, hole 0.279, Top Layer to Bottom Layer, 100 vias
v2: diameter 1.1, hole 0.56, Top Layer to Bottom Layer, 3 vias
v3: diameter 0.508, hole 0.279, Top Layer to Bottom Layer, 3 vias
v4: diameter 1.092, hole 0.559, Top Layer to Bottom Layer, 2 vias

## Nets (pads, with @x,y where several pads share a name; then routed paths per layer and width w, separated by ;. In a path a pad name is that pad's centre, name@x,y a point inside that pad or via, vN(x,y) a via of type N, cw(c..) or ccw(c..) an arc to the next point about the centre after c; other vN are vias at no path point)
3V3: C1.2 C2.2 C3.2 C4.2 C5.2 C6.1 C8.2 C9.2 C10.2 C15.1 C19.2 C22.2 C23.2 C24.2 J7.1 J11.1 J13.1 J16.2 L1.2 R2.2 R3.2 R4.2 R27.2 R28.2 R30.2 R31.2 R32.2 R33.2 R34.2 SD1.4 U1.6 U1.11 U1.19 U1.22 U1.28 U1.50 U1.75 U1.100 U2.1 U2.6 U4.3 U7.1 | length 275.5
  Top Layer w0.254: R2.2@-58.611,51.82 -58.484,51.82 -57.691,51.026 -56.531,51.026 C3.2@-55.738,50.233 ; C3.2@-55.611,50.233 C3.2@-55.738,50.233 ; v1(-55.579,49.187) -55.579,50.074 C3.2@-55.738,50.233 ; U1.50@-54.861,36.076 -55.29,36.076 -55.311,36.055 C4.2@-55.311,33.62 -55.418,33.726 -58.782,33.726 -59.411,34.355 -59.411,44.726 -58.284,45.853 -57.788,45.853 -56.573,47.067 -54.87,47.067 U1.28@-54.861,47.076 ; C5.2@-53.398,51.826 C5.2@-53.398,51.699 ; U1.22@-51.811,49.626 -51.82,49.635 -51.82,50.797 -52.028,51.005 -52.703,51.005 C5.2@-53.398,51.699 ; C10.2@-50.83,12.326 -50.83,12.453 -47.411,15.873 -47.411,24.226 ; U1.19@-50.311,49.626 -50.302,49.635 -50.302,50.815 -50.113,51.005 -49.512,51.005 -48.818,51.699 C24.2@-48.818,51.826 -48.818,54.726 ; U1.11@-46.311,49.626 -46.311,47.354 -46.162,47.205 -45.132,47.205 -43.811,48.526 U1.6@-43.811,49.626 -43.802,49.635 -43.802,50.869 C6.1@-42.638,52.033 ; R3.2@-45.911,26.544 R4.2@-47.411,26.544 -47.411,24.226 ; v1(-45.811,25.326) -46.311,25.326 -47.411,24.226 ; U2.6@-44.761,52.026 -44.754,52.033 C6.1@-42.638,52.033 ; U2.1@-44.761,53.626 -44.711,53.676 -44.711,54.726 ; U2.6@-44.661,52.026 U2.1@-44.661,53.626 ; v1(-43.311,25.326) -43.254,25.383 -43.064,25.383 J7.1@-41.091,27.356 ; J13.1@-42.211,69.226 -42.211,69.384 -40.178,71.417 -40.178,74.468 -38.811,75.835 ; -42.011,9.326 SD1.4@-42.011,13.726 ; U1.75@-41.311,34.526 -41.311,33.526 -40.811,33.026 C1.2@-40.811,32.226 v1@-40.811,29.935 ; U1.100@-39.761,48.076 -39.761,49.034 -40.63,49.903 -40.63,51.779 -40.884,52.033 C2.2@-41.011,52.033 C6.1@-42.511,52.033 C6.1@-42.638,52.033 ; v1(-39.654,54.726) -44.711,54.726 ; C15.1@-38.818,78.526 -38.818,78.572 -38.564,78.826 -35.011,78.826 ; C15.1@-38.811,78.572 -38.811,75.835 ; -38.259,10.278 -38.195,10.278 v1(-37.651,9.734) ; v1(-37.73,54.722) -37.726,54.726 -36.611,54.726 ; U4.3@-37.399,75.835 -38.811,75.835 ; -36.611,55.39 -33.707,55.39 -32.934,54.616 -32.934,54.077 J16.2@-32.68,53.823 -32.68,53.569 -31.594,52.484 -31.594,49.907 -31.838,49.663 -31.973,49.663 -32.586,49.05 C23.2@-32.586,48.923 -32.586,46.944 -32.413,46.771 U7.1@-32.361,46.771 ; -33.961,30.876 -33.807,30.876 -32.311,32.372 J11.1@-32.311,32.626 ; C3.2@-55.738,50.233 -55.484,50.487 -54.737,50.487 -53.779,51.445 -53.652,51.445 C5.2@-53.398,51.699 ; C5.2@-53.398,51.699 -53.211,51.886 -53.211,53.126 -51.611,54.726 -48.818,54.726 ; -48.818,54.726 -44.711,54.726
  Top Layer w0.5: C10.2@-50.83,12.326 C9.2@-50.83,10.826 C8.2@-50.83,9.326 -42.011,9.326 -39.211,9.326 -38.259,10.278 -32.611,15.926 -32.611,29.526 -33.961,30.876 -35.411,32.326 v4(-35.411,40.326) ; R28.2@-39.625,84.562 -39.644,84.581 -39.644,86.466 L1.2@-39.936,86.759 ; v4(-35.411,45.226) -35.411,46.693 -36.611,47.893 -36.611,54.726 -36.611,55.39 -36.611,57.226 -36.611,70.226 -35.011,71.826 -35.011,78.826 -35.011,86.087 -35.69,86.766 -37.295,86.766 C22.2@-37.303,86.759 L1.2@-39.936,86.759 ; C19.2@-33.988,86.773 -33.238,86.773 -31.937,88.074 -31.937,91.166 -32.308,91.538 -32.439,91.669 R27.2@-32.566,91.669 ; L1.2@-39.936,86.759 -41.886,86.759 L1.2@-42.244,87.116 -40.294,87.116 L1.2@-39.936,86.759
  Bottom Layer w0.254: v1(-56.605,47.036) -56.605,48.696 -56.171,49.13 -55.636,49.13 v1(-55.579,49.187) ; v1(-45.811,25.326) v1(-43.311,25.326) ; J7.1@-41.091,27.356 -42.024,28.289 -42.024,28.951 -41.11,29.864 -40.933,29.864 v1(-40.876,29.921) ; v1(-39.654,54.726) -39.651,54.724 -37.733,54.724 v1(-37.73,54.722) ; R34.2@-39.337,9.731 -39.334,9.734 v1(-37.651,9.734)
  Bottom Layer w0.5: R30.2@-45.441,9.731 R31.2@-43.906,9.731 R32.2@-42.388,9.731 R33.2@-40.862,9.731 R34.2@-39.337,9.731 ; v4(-35.411,40.326) v4(-35.411,45.226)
"5V INV A": C20_B.2 IC2_B.16 J1.1 J2.1 | length 72
  Top Layer w0.254: J1.1@-19.111,96.686 J1.1@-19.111,101.026 -19.111,103.095 -17.346,104.86 -0.881,104.86 -0.571,104.55 -0.571,95.969 -4.324,92.216 -4.324,89.46 -3.432,88.568 -3.432,87.426 -2.045,86.04 -2.045,79.167 -3.019,78.194 -11.644,78.194 v1@-12.63,79.179 ; v1@-12.63,79.282 IC2_B.16@-12.63,80.673 ; J2.1@-7.828,87.511 J2.1@-3.499,87.511
  Bottom Layer w0.254: v1@-12.659,79.282 -12.655,79.282 -12.603,79.335 -12.603,79.355 -12.478,79.479 C20_B.2@-12.478,80.368
  other v1: -12.659,79.198
"5V INV B": C13.2 C14.2 C20_A.2 IC2_A.16 J5.1 J6.1 J12.1 U7.16 | length 108.5
  Top Layer w0.254: U7.16@-23.061,46.771 -23.061,48.702 C13.2@-23.039,48.725 -23.039,50.226 C14.2@-23.055,50.242 -23.055,50.369 -15.854,57.57 J12.1@-6.941,57.57 ; IC2_A.16@-21.36,28.449 -21.273,28.537 -21.273,29.872 -21.273,30.161 -19.116,32.317 -6.002,32.317 -4.311,30.626 ; J6.1@-7.74,29.726 J6.1@-3.411,29.726 ; J12.1@-7.73,57.653 -6.941,57.653 J12.1@-3.401,57.653 -3.158,57.41 -2.595,57.41 -1.911,56.726 -1.911,50.426 -2.293,50.044 -3.493,50.044 -4.511,49.026 -4.511,46.426 -3.311,45.226 -2.211,45.226 -1.885,44.901 -1.885,36.575 -2.034,36.426 -3.911,36.426 -4.311,36.026 -4.311,30.626 ; J5.1@-5.211,11.536 J5.1@-5.211,15.876 -5.211,18.729 -3.802,20.138 -2.661,20.138 -1.971,20.828 -1.971,28.21 -3.411,29.649 J6.1@-3.411,29.726 ; -4.311,30.626 J6.1@-3.411,29.726
  Bottom Layer w0.254: C20_A.2@-21.519,28.826 -21.3,29.045 v1(-21.3,29.872)
12V: C12.2 J10.1 R9.2 R10.2 R11.2 R12.2 R13.2 U3.1 | length 45.3
  Top Layer w0.254: R12.2@-58.211,96.213 -58.165,96.213 R12.2@-57.911,96.467
  Top Layer w0.5: R11.2@-55.469,83.168 -55.911,82.726 -55.911,82.026 ; R11.2@-55.211,83.426 R9.2@-51.411,83.426 ; -54.711,94.226 -55.211,94.726 C12.2@-55.211,96.133 -55.251,96.173 -58.171,96.173 R12.2@-58.211,96.213 -58.338,96.213 -59.211,95.34 -59.211,85.326 -55.911,82.026 ; J10.1@-52.282,69.326 J10.1@-56.611,69.326 -57.877,70.592 -57.877,75.851 -57.053,76.675 -56.728,76.675 -55.904,77.499 -55.904,79.819 -55.911,79.826 -55.911,82.026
